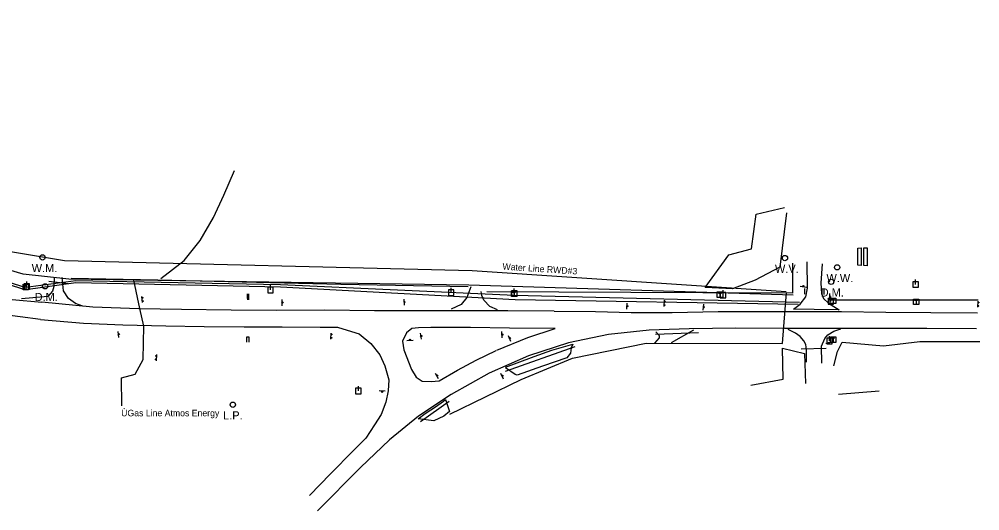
# Model space of a CAD drawing. Extents: x 19405533 to 19432306, y 137070 to 200991.
# Drawn here: x 19430925 to 19432306, y 137070 to 137776 of the extents above; entities that cross this region are included whole.
import ezdxf

# ---------------------------------------------------------------- set-up
doc = ezdxf.new("R2010")
doc.units = 0
for name, color, linetype in [('sv_Bituminous Area_x_s', 7, 'Continuous'), ('sv_Concrete Area_x_s', 7, 'Continuous'), ('sv_Drainage Structures_x_s', 7, 'Continuous'), ('sv_Fence Existing_x_s', 7, 'Continuous'), ('sv_Gas Utility Label_x_n', 7, 'Continuous'), ('sv_Gas Utility_x_n', 7, 'Continuous'), ('sv_Pavement Edge_x_s', 7, 'Continuous'), ('sv_Poles Utility_x_n', 7, 'Continuous'), ('sv_Private Road_x_s', 7, 'Continuous'), ('sv_Signs Billboards_x_s', 7, 'Continuous'), ('sv_Telephone Line_x_n', 7, 'Continuous'), ('sv_Terrace Lines_x_s', 7, 'Continuous'), ('sv_Treeline_x_s', 7, 'Continuous'), ('sv_Water Line Label_x_n', 7, 'Continuous'), ('sv_Water Line_x_n', 7, 'Continuous')]:
    doc.layers.add(name, color=color, linetype=linetype)

msp = doc.modelspace()

# ---------------------------------------------------------------- linework, layer by layer
at = {"layer": 'sv_Bituminous Area_x_s'}
for points in [[(19431624.2, 137276), (19431641, 137282.4), (19431665.3, 137291.5), (19431690.5, 137300.8), (19431721, 137309.4), (19431718.5, 137303.9), (19431717.6, 137296.1), (19431712.2, 137289.4), (19431677.3, 137277.5), (19431640.9, 137264.6), (19431637.8, 137265.6), (19431624.3, 137275.1)], [(19431538.1, 137229.8), (19431543.4, 137212.7), (19431535.3, 137205.8), (19431521.2, 137199.3), (19431498.6, 137201.9), (19431508.7, 137209.7), (19431523.6, 137219.4), (19431535.2, 137227.1), (19431538.1, 137229.8)]]:
    msp.add_lwpolyline(points, dxfattribs=at)
at = {"layer": 'sv_Concrete Area_x_s'}
for points in [[(19432130.6, 137447.4), (19432135.3, 137447.6), (19432135.1, 137422.4), (19432130.7, 137422.6), (19432130.6, 137447.4)], [(19432143.8, 137422.1), (19432139.1, 137422.3), (19432139.3, 137447.5), (19432143.9, 137447.5), (19432143.8, 137422.1)]]:
    msp.add_lwpolyline(points, dxfattribs=at)
at = {"layer": 'sv_Drainage Structures_x_s'}
for p, q in [((19430995.3, 137396), (19430967.7, 137399.5)), ((19432053.8, 137389.1), (19432053.7, 137380.9)), ((19432082.1, 137380.8), (19432082.2, 137389.1)), ((19431252.8, 137381.5), (19431252.9, 137374.7)), ((19431255.3, 137374.7), (19431255.2, 137381.5)), ((19431252.6, 137374.1), (19431255.5, 137374.1)), ((19431901.4, 137325.5), (19431839.5, 137323)), ((19431723.9, 137305.6), (19431623.8, 137270.1)), ((19432084.8, 137302.8), (19432049, 137302.1)), ((19431501.8, 137198), (19431543.2, 137227.2))]:
    msp.add_line(p, q, dxfattribs=at)
msp.add_lwpolyline([(19431252.5, 137312.2), (19431252.5, 137319), (19431252.4, 137319.8), (19431255.2, 137319.8), (19431255.1, 137319.1), (19431255.1, 137312.2)], dxfattribs=at)
at = {"layer": 'sv_Fence Existing_x_s'}
msp.add_line((19432102.8, 137237.5), (19432161.2, 137242.4), dxfattribs=at)
for points in [[(19432036.5, 137425.8), (19432036.5, 137382.8), (19431907.7, 137382.9), (19431597.3, 137384.4)], [(19430999.9, 137404.3), (19431124.2, 137401.8), (19431387.3, 137395.6), (19431570.3, 137392.2)], [(19432303.3, 137372.6), (19432090.2, 137372.5), (19432090.1, 137382)], [(19432095.9, 137278.3), (19432101.4, 137298.5), (19432108, 137312.2), (19432167.6, 137307.1), (19432219.4, 137312.9), (19432305.8, 137312.9)]]:
    msp.add_lwpolyline(points, dxfattribs=at)
at = {"layer": 'sv_Gas Utility_x_n'}
for points in [[(19432037.6, 137379.6), (19431571.4, 137393.9), (19430996.6, 137402.9), (19430930.7, 137410.1), (19430758.5, 137460.5), (19430663.5, 137488), (19430639.7, 137504.2), (19430624.7, 137558.5)], [(19432037.6, 137379.6), (19431571.4, 137393.9), (19430996.6, 137402.9), (19430930.7, 137410.1), (19430758.5, 137460.5), (19430663.5, 137488), (19430639.7, 137504.2), (19430624.7, 137558.5)], [(19432037.6, 137379.6), (19431571.4, 137393.9), (19430996.6, 137402.9), (19430930.7, 137410.1), (19430758.5, 137460.5), (19430663.5, 137488), (19430639.7, 137504.2), (19430624.7, 137558.5)], [(19431072.7, 137220.5), (19431072.1, 137261.1), (19431091.6, 137266.1), (19431103.5, 137287), (19431104.4, 137335.3), (19431098.4, 137360.6), (19431089.8, 137401.2)], [(19431072.7, 137220.5), (19431072.1, 137261.1), (19431091.6, 137266.1), (19431103.5, 137287), (19431104.4, 137335.3), (19431098.4, 137360.6), (19431089.8, 137401.2)], [(19431072.7, 137220.5), (19431072.1, 137261.1), (19431091.6, 137266.1), (19431103.5, 137287), (19431104.4, 137335.3), (19431098.4, 137360.6), (19431089.8, 137401.2)]]:
    msp.add_lwpolyline(points, dxfattribs=at)
at = {"layer": 'sv_Pavement Edge_x_s'}
msp.add_line((19431894.3, 137329.3), (19431862.4, 137311.4), dxfattribs=at)
for points in [[(19430955.9, 137344.5), (19430896.8, 137352.3), (19430838.8, 137362.5), (19430781.7, 137375.7), (19430719.1, 137392.7), (19430658.5, 137411.6), (19430606.8, 137428), (19430580.7, 137438.5), (19430570.8, 137444.4), (19430519, 137465.7), (19430462.3, 137491.8), (19430404.6, 137520.8), (19430349.7, 137551.8), (19430296.3, 137584), (19430242.5, 137620.2), (19430192.6, 137656.7), (19430142.4, 137696.4), (19430097.1, 137735.7), (19430053.5, 137776.4)], [(19430109, 137756.6), (19430157.5, 137714.6), (19430207.6, 137675.6), (19430253.3, 137642.2), (19430306.1, 137607), (19430357.3, 137575.5), (19430410.8, 137545.6), (19430462.6, 137519.1), (19430518.1, 137492.8), (19430571.1, 137470.7), (19430625.1, 137449.2), (19430682, 137429.6), (19430739.6, 137411.9), (19430797.1, 137396.7), (19430858.3, 137383.3), (19430914.9, 137373.7), (19430957.8, 137369.5)], [(19432079.2, 137424.9), (19432077.3, 137396.9), (19432078.4, 137382.1), (19432081.2, 137374.8), (19432088.3, 137368), (19432103.5, 137358.4), (19432067.6, 137359.1), (19432038, 137359.6), (19432047.6, 137366.6), (19432055.9, 137377.1), (19432058.3, 137389.8), (19432057.6, 137427.5)], [(19431694.2, 137356.9), (19431627.3, 137357.1), (19431570.3, 137357), (19431500.1, 137357.1), (19431435.9, 137357.1), (19431364.5, 137357.9), (19431294.4, 137357.6), (19431229.8, 137358.1), (19431158.6, 137359.1), (19431097, 137360), (19431030.9, 137362.4), (19430957.8, 137369.5)], [(19431694.2, 137356.9), (19431753.6, 137356), (19431804.5, 137355), (19431863.6, 137354.9), (19431929.7, 137356.1), (19431986.1, 137356.2), (19432033, 137356.4), (19432107.2, 137356), (19432170.8, 137355.3), (19432235.4, 137355), (19432302.3, 137354.4)], [(19430955.9, 137344.5), (19431017.6, 137339.6), (19431074, 137336.9), (19431135.8, 137335.5), (19431190.9, 137334.8), (19431248.4, 137334.3), (19431303.1, 137334.1), (19431357.8, 137333.7), (19431382.6, 137333.5), (19431396.7, 137329.6), (19431413.8, 137324), (19431430.7, 137310.1), (19431443.4, 137293.9), (19431450.7, 137278), (19431456.2, 137257.8), (19431455.5, 137242.3), (19431452.1, 137225.8), (19431445.2, 137208.1), (19431436, 137193.2), (19431423.4, 137174.2), (19431405.4, 137156.3), (19431372.6, 137123.1), (19431342.6, 137091.9)], [(19431611.5, 137300.6), (19431656.1, 137318.7), (19431695.4, 137331.6), (19431629.7, 137332.5), (19431573.8, 137333), (19431516.8, 137333.2), (19431499.1, 137332.9), (19431489.6, 137331.6), (19431481.7, 137325.7), (19431476, 137313.5), (19431478.1, 137301.3), (19431489, 137273), (19431495.8, 137261.7), (19431504.1, 137256.2), (19431517.1, 137255.5), (19431528.7, 137256.4), (19431555.2, 137272.1), (19431582, 137286.4), (19431610.6, 137300.2)], [(19432301.3, 137331.3), (19432229.5, 137331.7), (19432156.8, 137331.8), (19432106.2, 137331.8), (19432024.9, 137331.9), (19431955.3, 137332.3), (19431888.1, 137331.1), (19431830.5, 137329.3), (19431772.1, 137323), (19431714.5, 137311.1), (19431657.3, 137292.5), (19431600.7, 137267.4)], [(19431840.1, 137326.9), (19431845.2, 137321.8), (19431845, 137318.3), (19431838.2, 137310.5)], [(19432056.5, 137283.2), (19432056.7, 137300.9), (19432055.9, 137309), (19432053, 137314.2), (19432047.7, 137320.3), (19432040.8, 137325.1), (19432030.2, 137330.4)], [(19432078.8, 137281.8), (19432078.5, 137306.2), (19432083, 137317.2), (19432087.4, 137322.8), (19432096.1, 137327.8), (19432106, 137331.2)], [(19431600.7, 137267.4), (19431545.8, 137237), (19431499, 137205.7), (19431457.4, 137171.6), (19431415.8, 137132.2), (19431354.1, 137069.8)]]:
    msp.add_lwpolyline(points, dxfattribs=at)
at = {"layer": 'sv_Poles Utility_x_n'}
for p, q in [((19432213.6, 137395.1), (19432213.6, 137402.1)), ((19430932.1, 137396.2), (19430932.1, 137396.2)), ((19430936.1, 137392.3), (19430936.1, 137399.3)), ((19431282.3, 137391.1), (19431282.4, 137391.2)), ((19431286.3, 137387.2), (19431286.3, 137394.3)), ((19431546, 137383.4), (19431546, 137390.4)), ((19431636.8, 137382.1), (19431636.8, 137389.2)), ((19432209.6, 137399), (19432209.7, 137399.1)), ((19431542, 137387.2), (19431542.1, 137387.3)), ((19431632.8, 137386), (19431632.9, 137386.1)), ((19431932.8, 137383.6), (19431932.9, 137383.7)), ((19431936.8, 137379.8), (19431936.8, 137386.8)), ((19432087.7, 137374.6), (19432087.7, 137374.7)), ((19432091.7, 137370.7), (19432091.7, 137377.7)), ((19432089.8, 137313.9), (19432089.8, 137320.9)), ((19432085.8, 137317.8), (19432085.9, 137317.9)), ((19431408.7, 137245.8), (19431408.8, 137245.9)), ((19431412.7, 137242), (19431412.7, 137249))]:
    msp.add_line(p, q, dxfattribs=at)
for points in [[(19430932.1, 137388.2), (19430940, 137388.2), (19430940, 137396.2), (19430932.1, 137396.2)], [(19431282.3, 137383.2), (19431290.3, 137383.2), (19431290.3, 137391.2), (19431282.3, 137391.2)], [(19432209.6, 137391.1), (19432217.6, 137391.1), (19432217.6, 137399.1), (19432209.6, 137399.1)], [(19431542, 137379.3), (19431550, 137379.3), (19431550, 137387.3), (19431542, 137387.3)], [(19431632.8, 137378.1), (19431640.8, 137378.1), (19431640.8, 137386.1), (19431632.8, 137386.1)], [(19431932.8, 137375.7), (19431940.8, 137375.7), (19431940.8, 137383.7), (19431932.8, 137383.7)], [(19432087.7, 137366.7), (19432095.7, 137366.7), (19432095.7, 137374.7), (19432087.7, 137374.7)], [(19432085.8, 137309.9), (19432093.8, 137309.9), (19432093.8, 137317.9), (19432085.8, 137317.9)], [(19431408.7, 137237.9), (19431416.7, 137237.9), (19431416.7, 137245.9), (19431408.7, 137245.9)]]:
    msp.add_lwpolyline(points, close=True, dxfattribs=at)
for centre in [(19432092.2, 137398.9), (19430962.3, 137392.4), (19431232.2, 137222.2)]:
    msp.add_circle(centre, 3.78, dxfattribs=at)
at = {"layer": 'sv_Private Road_x_s'}
for points in [[(19430975.3, 137405.1), (19430975, 137392), (19430972.9, 137385.3), (19430966.5, 137378), (19430928.6, 137374.3)], [(19431016.6, 137364), (19431006, 137367.6), (19430996.2, 137374.8), (19430988.7, 137386.1), (19430986.9, 137404.9)], [(19431574.4, 137391.7), (19431568.4, 137376.3), (19431560.5, 137366.1), (19431546, 137359.4)], [(19431612.5, 137358.4), (19431601.7, 137363.2), (19431593, 137372.3), (19431590.1, 137379.1), (19431589.3, 137384.8)]]:
    msp.add_lwpolyline(points, dxfattribs=at)
at = {"layer": 'sv_Signs Billboards_x_s'}
for p, q in [((19432047.7, 137392.4), (19432056.5, 137391.3)), ((19431102.6, 137369), (19431101.5, 137377.8)), ((19431302.8, 137373.5), (19431302.6, 137364.6)), ((19431477.8, 137374.1), (19431478.5, 137365.2)), ((19431798.4, 137368.4), (19431798.2, 137359.5)), ((19431852, 137363.5), (19431852.8, 137372.3)), ((19431908.8, 137366.9), (19431907.6, 137358.1)), ((19432302.9, 137362.3), (19432303.5, 137371.1)), ((19431067, 137327.7), (19431068.1, 137318.9)), ((19431373.2, 137316.4), (19431373.6, 137325.3)), ((19431501.4, 137325.2), (19431502.9, 137316.5)), ((19431618.4, 137327.4), (19431618.8, 137318.6)), ((19431627.8, 137321.8), (19431631.2, 137313.6)), ((19431482.4, 137314.3), (19431491.3, 137314.8)), ((19432084.4, 137310.5), (19432093.2, 137309.7)), ((19431122.7, 137294.3), (19431122, 137285.5)), ((19431522.8, 137267.5), (19431527.1, 137259.8)), ((19431617.1, 137267.6), (19431620.8, 137259.5)), ((19431451.2, 137241.5), (19431442.4, 137242.1))]:
    msp.add_line(p, q, dxfattribs=at)
for centre, radius in [((19432052.2, 137392.7), 0.885), ((19431102.4, 137376), 0.632), ((19431103, 137371), 0.632), ((19431303.6, 137369), 0.885), ((19431479, 137369.7), 0.885), ((19431799.2, 137363.9), 0.885), ((19431852.8, 137365.3), 0.632), ((19431853.3, 137370.4), 0.632), ((19431909.1, 137362.4), 0.885), ((19432303.6, 137364.2), 0.632), ((19432304, 137369.2), 0.632), ((19431068.4, 137323.4), 0.885), ((19431374.1, 137323.3), 0.632), ((19431503, 137321), 0.885), ((19431619.5, 137323), 0.885), ((19431373.9, 137318.3), 0.632), ((19431486.8, 137315.5), 0.885), ((19431630.3, 137318.1), 0.885), ((19432088.8, 137311), 0.885), ((19431122, 137292.4), 0.632), ((19431121.6, 137287.4), 0.632), ((19431525.8, 137264.1), 0.885), ((19431619.8, 137263.9), 0.885), ((19431446.8, 137240.9), 0.885)]:
    msp.add_circle(centre, radius, dxfattribs=at)
at = {"layer": 'sv_Telephone Line_x_n'}
for points in [[(19430933.5, 137387.4), (19430637.2, 137480.5), (19430636.8, 137486.6)], [(19430933.9, 137390.6), (19430638.9, 137482.8), (19430637.4, 137486.7)], [(19430932.6, 137393.6), (19430936.7, 137393.6), (19430934.7, 137393.6), (19430934.7, 137387.4), (19430930.7, 137387.4), (19430930.7, 137395.4), (19430938.6, 137395.4), (19430938.6, 137387.4), (19430934.7, 137387.4)], [(19432046.7, 137369.1), (19431637, 137379.2), (19431300.6, 137394.6), (19431006.7, 137400.5), (19430934.9, 137390.7)], [(19432046.7, 137369.1), (19431637, 137379.2), (19431300.6, 137394.6), (19431006.7, 137400.5), (19430934.9, 137390.7)], [(19432046.7, 137369.1), (19431637, 137379.2), (19431300.6, 137394.6), (19431006.7, 137400.5), (19430934.9, 137390.7)], [(19432044.8, 137366.4), (19431637.9, 137373), (19431300.6, 137391.2), (19431006.4, 137397.2), (19430934.9, 137387.3)], [(19432044.8, 137366.4), (19431637.9, 137373), (19431300.6, 137391.2), (19431006.4, 137397.2), (19430934.9, 137387.3)], [(19432044.8, 137366.4), (19431637.9, 137373), (19431300.6, 137391.2), (19431006.4, 137397.2), (19430934.9, 137387.3)], [(19431634.4, 137384), (19431638.5, 137384), (19431636.5, 137384), (19431636.5, 137377.7), (19431632.5, 137377.7), (19431632.5, 137385.7), (19431640.5, 137385.7), (19431640.5, 137377.7), (19431636.5, 137377.7)], [(19431930.3, 137382.6), (19431934.4, 137382.6), (19431932.4, 137382.6), (19431932.4, 137376.3), (19431928.4, 137376.3), (19431928.4, 137384.3), (19431936.4, 137384.3), (19431936.4, 137376.3), (19431932.4, 137376.3)], [(19432092.8, 137373.9), (19432096.9, 137373.9), (19432094.9, 137373.9), (19432094.9, 137367.6), (19432090.9, 137367.6), (19432090.9, 137375.6), (19432098.9, 137375.6), (19432098.9, 137367.6), (19432094.9, 137367.6)], [(19432212.2, 137372.3), (19432216.3, 137372.3), (19432214.3, 137372.3), (19432214.3, 137366.1), (19432210.3, 137366.1), (19432210.3, 137374.1), (19432218.3, 137374.1), (19432218.3, 137366.1), (19432214.3, 137366.1)], [(19432092.9, 137317.9), (19432097, 137317.9), (19432095, 137317.9), (19432095, 137311.7), (19432091, 137311.7), (19432091, 137319.7), (19432099, 137319.7), (19432099, 137311.7), (19432095, 137311.7)]]:
    msp.add_lwpolyline(points, dxfattribs=at)
at = {"layer": 'sv_Terrace Lines_x_s'}
msp.add_lwpolyline([(19431128.6, 137403.6), (19431162.4, 137429.5), (19431185.1, 137458.1), (19431204.3, 137491.4), (19431219.3, 137523.6), (19431234.6, 137559)], dxfattribs=at)
at = {"layer": 'sv_Treeline_x_s'}
for points in [[(19432028.1, 137497.9), (19432018.3, 137419.9), (19431982.9, 137401.4), (19431950.4, 137388.6), (19431911.3, 137390.9), (19431945.1, 137437.8), (19431977.7, 137446.1), (19431984.6, 137495.9), (19432025.1, 137505.9)], [(19431976.5, 137250.3), (19432023.3, 137258.9), (19432022.1, 137303.6), (19432054, 137295.9), (19432055.4, 137252.6)]]:
    msp.add_lwpolyline(points, dxfattribs=at)
at = {"layer": 'sv_Water Line_x_n'}
for points in [[(19432027.6, 137384.4), (19431576.3, 137414.6), (19430990.4, 137429), (19430760.2, 137467.5), (19430666.4, 137498.8), (19430617.6, 137512.2), (19430579, 137548.3)], [(19432027.6, 137384.4), (19431576.3, 137414.6), (19430990.4, 137429), (19430760.2, 137467.5), (19430666.4, 137498.8), (19430617.6, 137512.2), (19430579, 137548.3)], [(19432027.6, 137384.4), (19431576.3, 137414.6), (19430990.4, 137429), (19430760.2, 137467.5), (19430666.4, 137498.8), (19430617.6, 137512.2), (19430579, 137548.3)], [(19431544.2, 137208.8), (19431646.4, 137258.4), (19431720.3, 137289), (19431826.1, 137310.8), (19432022.2, 137310), (19432027.9, 137383.3)], [(19431544.2, 137208.8), (19431646.4, 137258.4), (19431720.3, 137289), (19431826.1, 137310.8), (19432022.2, 137310), (19432027.9, 137383.3)], [(19431544.2, 137208.8), (19431646.4, 137258.4), (19431720.3, 137289), (19431826.1, 137310.8), (19432022.2, 137310), (19432027.9, 137383.3)]]:
    msp.add_lwpolyline(points, dxfattribs=at)
for centre in [(19430958.6, 137434), (19432025.8, 137433), (19432100.8, 137419.7)]:
    msp.add_circle(centre, 3.78, dxfattribs=at)

# ---------------------------------------------------------------- texts
at = {"layer": 'sv_Gas Utility Label_x_n'}
msp.add_text('ÙGas Line Atmos Energy', height=9.35, dxfattribs=at).set_placement((19431071.7, 137205.6))
at = {"layer": 'sv_Poles Utility_x_n'}
for s, p in [('D.M.', (19432077.1, 137377.7)), ('D.M.', (19430947.3, 137371.2)), ('L.P.', (19431218.2, 137201))]:
    msp.add_text(s, height=11.8, dxfattribs=at).set_placement(p)
at = {"layer": 'sv_Water Line Label_x_n'}
msp.add_text('Water Line RWD#3', height=9.35, rotation=356.1674, dxfattribs=at).set_placement((19431619.5, 137416.5))
at = {"layer": 'sv_Water Line_x_n'}
for s, p in [('W.M.', (19430943.1, 137412.8)), ('W.V.', (19432011.4, 137411.8)), ('W.W.', (19432085.4, 137398.4))]:
    msp.add_text(s, height=11.8, dxfattribs=at).set_placement(p)

doc.saveas('drawing.dxf')
